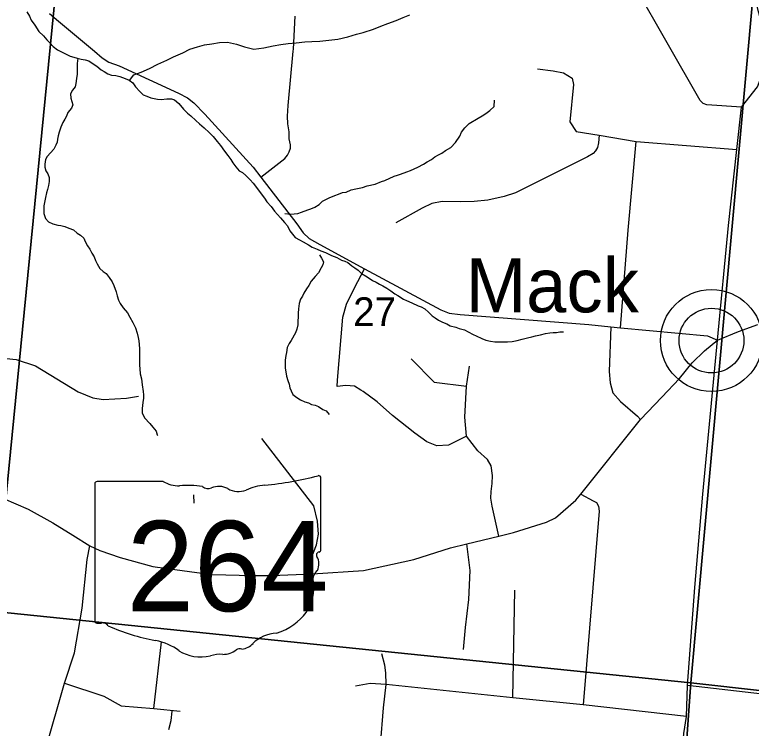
# Model space of a CAD drawing. Extents: x 0 to 43.4, y -8.1 to 22.
# Drawn here: x 4.976 to 6.05, y 19.427 to 20.468 of the extents above; entities that cross this region are included whole.
import ezdxf

# ---------------------------------------------------------------- set-up
doc = ezdxf.new("R2010")
doc.units = 0
for name, color, linetype in [('GM_X_Corporation', 7, 'Continuous'), ('GM_X_County_Road', 7, 'Continuous'), ('GM_X_Minor_River', 7, 'Continuous'), ('GM_X_Section_Text', 7, 'Continuous'), ('GM_X_State_Location', 7, 'Continuous'), ('GM_X_State_Route', 7, 'Continuous'), ('GM_X_State_Shield', 7, 'Continuous'), ('GM_X_Township_Road', 7, 'Continuous'), ('GM_X_Unincorporated', 7, 'Continuous'), ('GM_X_Unincorporated_Location', 7, 'Continuous'), ('GM_X_Unincorporated_Text', 7, 'Continuous')]:
    doc.layers.add(name, color=color, linetype=linetype)

msp = doc.modelspace()

# ---------------------------------------------------------------- linework, layer by layer
at = {"layer": 'GM_X_Corporation'}
for points in [[(4.0476, 20.7082), (5.0456, 20.604), (4.9462, 19.5972), (3.9403, 19.703)], [(6.0521, 20.4929), (5.9616, 19.4927), (4.9462, 19.5972), (5.0456, 20.604)], [(7.0465, 20.3953), (6.9413, 19.3833), (5.9616, 19.4927), (6.0521, 20.4929)], [(5.9616, 19.4927), (5.8893, 18.4791), (4.8473, 18.579), (4.9462, 19.5972)], [(5.9616, 19.4927), (6.9413, 19.3833), (6.8431, 18.3799), (5.8893, 18.4791)]]:
    msp.add_lwpolyline(points, close=True, dxfattribs=at)
at = {"layer": 'GM_X_County_Road'}
for points in [[(6.0357, 20.3327), (5.9847, 20.3361), (5.9794, 20.3381), (5.975, 20.3428), (5.8326, 20.592), (5.8291, 20.6012), (5.8268, 20.6093), (5.8263, 20.6196), (5.8283, 20.6466), (5.8319, 20.6972), (5.8303, 20.7167), (5.8274, 20.7335), (5.8218, 20.7469), (5.8142, 20.7586), (5.8035, 20.7684), (5.779, 20.7844), (5.7029, 20.8343), (5.6968, 20.8432), (5.6908, 20.8537), (5.6869, 20.8655), (5.6878, 20.9)], [(6.0357, 20.3327), (6.0589, 20.3624), (6.0642, 20.3767), (6.0699, 20.4347), (6.0514, 20.507), (6.0739, 20.9)], [(5.0263, 20.4697), (5.0396, 20.4585), (5.092, 20.4145), (5.1031, 20.4047), (5.1132, 20.3988), (5.1282, 20.3934), (5.2144, 20.3532), (5.2275, 20.3464), (5.2368, 20.3393), (5.2531, 20.3229), (5.3235, 20.2455), (5.3348, 20.2308), (5.3873, 20.1625), (5.3964, 20.1497), (5.4053, 20.1411), (5.4206, 20.1323), (5.4859, 20.0972)], [(6.0003, 19.9928), (6.0164, 20.1603), (6.0288, 20.2712), (6.0357, 20.3327)], [(5.4859, 20.0972), (5.5972, 20.0373), (5.6092, 20.0324), (5.6251, 20.0304), (5.813, 20.0156), (5.8451, 20.0124)], [(5.8451, 20.0124), (5.8423, 19.9471), (5.8438, 19.9306), (5.8477, 19.916), (5.8588, 19.9035), (5.8836, 19.8822), (5.8884, 19.8771)], [(5.8451, 20.0124), (5.859, 20.011), (5.9861, 19.9993), (6.0003, 19.9928)], [(5.9168, 18.9788), (5.9313, 19.1438), (5.9319, 19.1508), (5.942, 19.2909), (5.9466, 19.3546), (5.9513, 19.4191), (5.9555, 19.4438), (5.9566, 19.4892), (5.9673, 19.632), (5.979, 19.7684), (6.0003, 19.9928)], [(4.8412, 18.9443), (4.8517, 18.9555), (4.8735, 18.9849), (4.8771, 18.9917), (4.8807, 19.0109), (4.8872, 19.0868), (4.8907, 19.1269), (4.8957, 19.1416), (4.9044, 19.1555), (4.9529, 19.2503), (4.9786, 19.304), (4.9807, 19.309), (5.0206, 19.3955), (5.0483, 19.4922), (5.0629, 19.5365), (5.074, 19.6019), (5.0812, 19.673), (5.0855, 19.6927)], [(7.1544, 19.3549), (7.0147, 19.3696), (6.8713, 19.3847), (6.7437, 19.3982), (6.635, 19.4142), (6.3486, 19.4465), (6.2939, 19.453), (6.2651, 19.4537), (6.2278, 19.458), (6.1978, 19.4615), (6.1234, 19.47), (6.0534, 19.478), (5.9566, 19.4892)]]:
    msp.add_lwpolyline(points, dxfattribs=at)
at = {"layer": 'GM_X_Minor_River'}
for points in [[(4.9934, 20.4719), (4.9974, 20.4657), (4.9998, 20.4599), (5.0049, 20.4525), (5.011, 20.4435), (5.0176, 20.4369), (5.0227, 20.431), (5.0275, 20.4263), (5.0319, 20.4212), (5.0382, 20.4168), (5.0442, 20.4135), (5.049, 20.4111), (5.0565, 20.4074), (5.0617, 20.4057), (5.0666, 20.4044), (5.0727, 20.403), (5.0787, 20.4021), (5.0836, 20.4004), (5.0903, 20.3963), (5.0955, 20.3927), (5.1017, 20.3876), (5.1062, 20.3848), (5.1114, 20.3815), (5.1167, 20.3798), (5.1231, 20.3789), (5.1291, 20.3775), (5.137, 20.3746), (5.1426, 20.3721), (5.1478, 20.3685), (5.1518, 20.3627), (5.158, 20.3556), (5.1631, 20.3509), (5.1684, 20.3488), (5.174, 20.3467), (5.1793, 20.3454), (5.1838, 20.3445), (5.1891, 20.3439), (5.1975, 20.3451), (5.2043, 20.3453), (5.2088, 20.3436), (5.2151, 20.3381), (5.222, 20.3298), (5.2275, 20.3243), (5.2327, 20.3203), (5.24, 20.3136), (5.2452, 20.3085), (5.2522, 20.3026), (5.2592, 20.2959), (5.2651, 20.2903), (5.2709, 20.2829), (5.2756, 20.2771), (5.2818, 20.2685), (5.2865, 20.2626), (5.2908, 20.2564), (5.2937, 20.2517), (5.2981, 20.2459), (5.3032, 20.24), (5.3077, 20.2376), (5.3128, 20.2332), (5.3191, 20.2269), (5.3234, 20.2218), (5.3282, 20.2159), (5.3336, 20.2085), (5.3398, 20.2), (5.3434, 20.1949), (5.3496, 20.1878), (5.3547, 20.1812), (5.3591, 20.1765), (5.3635, 20.1714), (5.3693, 20.1647), (5.3737, 20.1596), (5.3768, 20.1523), (5.3809, 20.1476), (5.3845, 20.1429), (5.3908, 20.1393), (5.3964, 20.1364), (5.4042, 20.132), (5.4094, 20.1284), (5.4166, 20.1259), (5.4222, 20.1234), (5.4289, 20.1209), (5.4375, 20.1164), (5.4454, 20.1135), (5.4521, 20.1098), (5.4569, 20.1081), (5.4614, 20.1061), (5.4673, 20.1013), (5.4718, 20.0985), (5.4766, 20.0949), (5.4814, 20.0902), (5.4896, 20.0853), (5.4974, 20.0801), (5.5026, 20.0773), (5.5078, 20.0748), (5.5127, 20.0724), (5.5182, 20.0687), (5.5242, 20.0651), (5.5301, 20.0607)], [(5.143, 20.3718), (5.1496, 20.3801), (5.16, 20.384), (5.1723, 20.3893), (5.1846, 20.3954), (5.1977, 20.4015), (5.2073, 20.4062), (5.2208, 20.4123), (5.2312, 20.4177), (5.2423, 20.4211), (5.2523, 20.4239), (5.263, 20.4251), (5.2744, 20.4271), (5.2858, 20.4279), (5.299, 20.4249), (5.3107, 20.4211), (5.3243, 20.4173), (5.3388, 20.4195), (5.3525, 20.4226), (5.3636, 20.4242), (5.3743, 20.4257), (5.3861, 20.4269), (5.3986, 20.4281), (5.4089, 20.4286), (5.4207, 20.4294), (5.434, 20.4309), (5.447, 20.432), (5.4615, 20.4354), (5.4742, 20.4392), (5.4837, 20.442), (5.4987, 20.4469), (5.5095, 20.4512), (5.5198, 20.455), (5.5321, 20.4593), (5.5421, 20.4635), (5.5517, 20.4678)], [(5.0676, 20.4042), (5.0667, 20.3964), (5.0669, 20.3903), (5.0666, 20.3812), (5.066, 20.3748), (5.065, 20.3672), (5.0637, 20.3627), (5.0601, 20.3575), (5.0569, 20.3523), (5.0574, 20.3462), (5.0588, 20.3412), (5.0605, 20.3362), (5.0584, 20.3313), (5.0533, 20.325), (5.0512, 20.3198), (5.0487, 20.3153), (5.0459, 20.3105), (5.043, 20.3037), (5.0405, 20.2966), (5.0392, 20.2909), (5.0383, 20.2864), (5.0377, 20.2819), (5.0357, 20.2774), (5.0328, 20.2714), (5.0281, 20.2662), (5.023, 20.2611), (5.0205, 20.2566), (5.0195, 20.2498), (5.0198, 20.2452), (5.0211, 20.2402), (5.024, 20.2356), (5.0261, 20.2302), (5.0259, 20.2245), (5.0249, 20.2188), (5.0236, 20.2128), (5.0223, 20.2079), (5.0205, 20.2011), (5.0196, 20.1962), (5.0182, 20.1887), (5.018, 20.1826), (5.0182, 20.1776), (5.0206, 20.1703), (5.025, 20.1656), (5.0313, 20.1627), (5.0385, 20.1606), (5.043, 20.1604), (5.0487, 20.1587), (5.0546, 20.1562), (5.0614, 20.1537), (5.0669, 20.149), (5.0718, 20.1461), (5.0765, 20.1418), (5.0787, 20.1368), (5.0819, 20.1306), (5.0851, 20.1259), (5.0883, 20.1197), (5.0916, 20.1147), (5.0933, 20.1093), (5.0958, 20.1043), (5.0997, 20.0977), (5.1049, 20.0933), (5.1093, 20.0901), (5.1137, 20.0843), (5.118, 20.078), (5.1201, 20.0726), (5.1236, 20.0634), (5.1249, 20.0577), (5.1273, 20.0515), (5.1294, 20.0465), (5.1338, 20.0402), (5.14, 20.0328), (5.1436, 20.0266), (5.1479, 20.0188), (5.1521, 20.0107), (5.1541, 20.0031), (5.1558, 19.9969), (5.1568, 19.9919), (5.1574, 19.9866), (5.1575, 19.9805), (5.1577, 19.9752), (5.1579, 19.968), (5.1576, 19.9615), (5.1578, 19.9562), (5.1584, 19.9512), (5.1589, 19.944), (5.1606, 19.9363), (5.1618, 19.9275), (5.163, 19.918), (5.1636, 19.913), (5.1634, 19.9085), (5.1624, 19.902), (5.1614, 19.893), (5.1615, 19.8869), (5.1651, 19.8795), (5.1728, 19.8713), (5.1771, 19.8658), (5.1819, 19.8603), (5.1836, 19.8546), (5.1838, 19.8537)], [(5.3697, 20.1776), (5.3785, 20.177), (5.3834, 20.1772), (5.3884, 20.1778), (5.3937, 20.1795), (5.403, 20.1833), (5.4076, 20.1847), (5.4134, 20.1872), (5.4196, 20.1907), (5.4243, 20.1955), (5.4343, 20.2005), (5.4424, 20.204), (5.4478, 20.2061), (5.4536, 20.2082), (5.4589, 20.2091), (5.4662, 20.2123), (5.4731, 20.2136), (5.4827, 20.2155), (5.4896, 20.218), (5.5015, 20.2206), (5.5107, 20.2245), (5.5153, 20.2258), (5.5292, 20.2322), (5.5338, 20.2339), (5.5384, 20.2353), (5.5473, 20.2384), (5.5526, 20.2405), (5.5584, 20.2429), (5.5634, 20.2454), (5.5716, 20.2497), (5.577, 20.2529), (5.5836, 20.2565), (5.5882, 20.2602), (5.5937, 20.2634), (5.5987, 20.2659), (5.6041, 20.2699), (5.6115, 20.2742), (5.6186, 20.2815), (5.6246, 20.2904), (5.6271, 20.2964), (5.6319, 20.3027), (5.6385, 20.309), (5.6513, 20.3169), (5.6571, 20.3201), (5.6626, 20.3237), (5.6684, 20.3281), (5.6747, 20.3339), (5.6754, 20.343)], [(5.4201, 20.1174), (5.4233, 20.1127), (5.4262, 20.1073), (5.4249, 20.1028), (5.4224, 20.0983), (5.4188, 20.0912), (5.4137, 20.0857), (5.4081, 20.079), (5.4045, 20.0727), (5.4013, 20.0679), (5.3973, 20.0615), (5.3952, 20.057), (5.3924, 20.0526), (5.3903, 20.0462), (5.3896, 20.0386), (5.389, 20.0322), (5.3884, 20.0151), (5.3871, 20.0091), (5.385, 20.0038), (5.3789, 19.9926), (5.3761, 19.9882), (5.3732, 19.9822), (5.3719, 19.975), (5.3709, 19.9705), (5.3703, 19.9636), (5.3701, 19.9564), (5.3703, 19.9519), (5.3709, 19.9469), (5.3722, 19.9404), (5.3742, 19.9339), (5.3759, 19.9285), (5.3769, 19.9235), (5.3787, 19.9189), (5.3815, 19.9138), (5.3871, 19.9091), (5.3923, 19.9059), (5.399, 19.903), (5.4039, 19.9013), (5.4087, 19.8992), (5.4136, 19.8979), (5.4185, 19.8962), (5.4252, 19.8918), (5.4297, 19.8898), (5.4344, 19.8843)], [(5.5301, 20.0607), (5.5346, 20.0579), (5.5427, 20.0527), (5.5472, 20.0506), (5.5547, 20.0473), (5.5641, 20.0432), (5.5685, 20.0415), (5.5738, 20.0387), (5.5793, 20.0336), (5.5844, 20.0284), (5.5889, 20.0253), (5.5937, 20.0221), (5.5993, 20.0192), (5.606, 20.0167), (5.6109, 20.0139), (5.6188, 20.0121), (5.624, 20.01), (5.6315, 20.0078), (5.6368, 20.005), (5.6442, 20.0013), (5.6487, 19.9992), (5.6569, 19.9955), (5.6629, 19.9927), (5.6693, 19.9913), (5.6758, 19.9907), (5.6879, 19.9903), (5.6944, 19.9904), (5.7012, 19.991), (5.7085, 19.9922), (5.7157, 19.9943), (5.7234, 19.9963), (5.7299, 19.9979), (5.7349, 19.9993), (5.7422, 20.0009), (5.7498, 20.0026), (5.7559, 20.0035), (5.7609, 20.0041), (5.7658, 20.0043), (5.7708, 20.0049), (5.7761, 20.0051)], [(5.2375, 19.755), (5.2371, 19.7672)], [(5.2006, 19.4248), (5.2037, 19.438), (5.2052, 19.4516)]]:
    msp.add_lwpolyline(points, dxfattribs=at)
at = {"layer": 'GM_X_State_Route'}
msp.add_line((5.1803, 19.6621), (5.2595, 19.6515), dxfattribs=at)
for points in [[(5.9928, 19.9866), (6.0003, 19.9928), (6.0309, 20.0057), (6.0594, 20.0157)], [(5.9191, 19.9096), (5.9451, 19.9372), (5.9633, 19.96), (5.9817, 19.9772), (5.9928, 19.9866)], [(5.2595, 19.6515), (5.2635, 19.651), (5.323, 19.6493), (5.3504, 19.6497), (5.4101, 19.6519), (5.4843, 19.6566), (5.5575, 19.6731), (5.6113, 19.6897), (5.6351, 19.6955), (5.6817, 19.707), (5.7032, 19.7123), (5.7513, 19.7271), (5.7644, 19.7337), (5.7938, 19.7596), (5.8011, 19.7683), (5.8884, 19.8771), (5.9191, 19.9096)], [(4.9594, 19.7617), (4.9954, 19.7464), (5.0314, 19.7266), (5.0605, 19.7084)], [(5.0605, 19.7084), (5.0855, 19.6927), (5.0998, 19.6859), (5.1295, 19.6757), (5.1773, 19.6625), (5.1803, 19.6621)]]:
    msp.add_lwpolyline(points, dxfattribs=at)
at = {"layer": 'GM_X_State_Shield'}
for p, q in [((5.0926, 19.7834), (5.0926, 19.5833)), ((5.1924, 19.7869), (5.0959, 19.7869)), ((5.4222, 19.6871), (5.4222, 19.7918)), ((5.4222, 19.6872), (5.4222, 19.6871))]:
    msp.add_line(p, q, dxfattribs=at)
for centre, major_axis, start_param, end_param in [((5.3048, 20.0597), (0.3495, 0), 4.814394, 5.042369), ((5.4185, 19.7923), (0.00367, 0), 6.141152, 7.989035), ((5.0964, 19.7838), (0.00382, 0), 1.712693, 3.28349), ((5.2154, 19.8101), (0.037, 0), 4.042523, 4.731795), ((5.2276, 19.6745), (0.133, 0), 1.404758, 1.657858), ((5.2578, 19.7849), (0.0107, 0), 3.836095, 5.185415), ((5.2735, 19.7618), (0.0222, 0), 0.950623, 2.079405), ((5.3022, 19.7935), (0.0267, 0), 4.081561, 5.145723), ((5.3494, 19.7257), (0.0703, 0), 1.699011, 2.107814), ((5.4183, 19.6867), (0.00393, 0), 5.05454, 6.418171), ((5.4213, 19.6795), (0.00568, 0), 1.883978, 3.671073), ((5.3852, 19.6662), (0.0341, 0), 5.934695, 6.695948), ((5.4353, 19.6433), (0.0248, 0), 2.387724, 3.262537), ((5.3244, 19.63), (0.0874, 0), 5.101752, 6.440018), ((5.0964, 19.5829), (0.00385, 0), 3.00124, 4.508301), ((5.097, 19.6033), (0.0294, 0), 4.665946, 4.897461), ((5.103, 19.5718), (0.0106, 0), 0.519207, 1.627899), ((5.2368, 19.7516), (0.2524, 0), 4.195997, 4.488961), ((5.3612, 19.5271), (0.0479, 0), 1.647645, 2.488434), ((5.1616, 19.4934), (0.079, 0), 0.823519, 1.323587), ((5.3006, 19.5639), (0.0282, 0), 4.937069, 5.64225), ((5.247, 19.5708), (0.0501, 0), 4.026481, 4.996735), ((5.2796, 19.5558), (0.0267, 0), 4.691044, 5.507374), ((5.3038, 19.5364), (0.00752, 0), 1.147584, 2.315152), ((5.276, 19.5016), (0.0412, 0), 1.495662, 1.94098)]:
    msp.add_ellipse(centre, major_axis=major_axis, ratio=0.8, start_param=start_param, end_param=end_param, dxfattribs=at)
at = {"layer": 'GM_X_Township_Road'}
for p, q in [((5.702, 19.4711), (5.7049, 19.6283)), ((5.1785, 19.4554), (5.1897, 19.5526))]:
    msp.add_line(p, q, dxfattribs=at)
for points in [[(5.3818, 20.4145), (5.3821, 20.4175), (5.3849, 20.4659)], [(5.3348, 20.2308), (5.3694, 20.2582), (5.3734, 20.2629), (5.3758, 20.2675), (5.3777, 20.2729), (5.3777, 20.2777), (5.3757, 20.2865), (5.3757, 20.2967), (5.3738, 20.3085), (5.3737, 20.3197), (5.3746, 20.3352), (5.3818, 20.4145)], [(5.7382, 20.3888), (5.7609, 20.3858), (5.776, 20.3828), (5.7887, 20.3751), (5.7903, 20.3661), (5.7853, 20.3115), (5.7943, 20.2975), (5.8278, 20.2918)], [(5.8278, 20.2918), (5.8268, 20.281), (5.8253, 20.274), (5.8226, 20.269), (5.8191, 20.2652), (5.811, 20.2602), (5.7058, 20.208), (5.6892, 20.2027), (5.6656, 20.1974), (5.6458, 20.1954), (5.6262, 20.1949), (5.5988, 20.1952), (5.584, 20.1923), (5.5699, 20.1857), (5.5313, 20.1641)], [(5.8278, 20.2918), (5.882, 20.2828), (6.0288, 20.2712)], [(5.859, 20.011), (5.8703, 20.1533), (5.882, 20.2828)], [(5.4802, 19.9201), (5.4714, 19.926), (5.4586, 19.9269), (5.4461, 19.9255), (5.4462, 19.9344), (5.4541, 20.0267), (5.4593, 20.0456), (5.4714, 20.0691), (5.4859, 20.0972)], [(4.8794, 19.9495), (4.9286, 19.9661), (4.9541, 19.9673), (4.9777, 19.9648), (5.006, 19.9555), (5.0683, 19.9175), (5.0895, 19.9089), (5.1048, 19.9061), (5.1389, 19.9081), (5.1561, 19.911)], [(5.5539, 19.9656), (5.5875, 19.9318), (5.6346, 19.926)], [(5.6817, 19.707), (5.672, 19.7507), (5.6699, 19.7626), (5.6704, 19.7719), (5.6717, 19.7838), (5.6722, 19.7954), (5.6706, 19.8093), (5.6653, 19.8189), (5.651, 19.8312), (5.6346, 19.8526), (5.6323, 19.8804), (5.6346, 19.926), (5.6387, 19.9552)], [(5.6346, 19.8526), (5.6081, 19.8398), (5.591, 19.8388), (5.5767, 19.8444), (5.5594, 19.8572), (5.5266, 19.8831), (5.5042, 19.9027), (5.4837, 19.9178), (5.4802, 19.9201)], [(5.4101, 19.6519), (5.4069, 19.6719), (5.416, 19.6942), (5.4188, 19.7097), (5.4174, 19.7288), (5.4119, 19.7512), (5.3363, 19.8496)], [(5.8011, 19.7683), (5.8191, 19.7583), (5.8239, 19.7559), (5.8271, 19.7505), (5.828, 19.7432), (5.8045, 19.4607)], [(5.63, 19.5413), (5.6332, 19.5735), (5.6381, 19.6144), (5.64, 19.6566), (5.6351, 19.6955)], [(5.5057, 19.3601), (5.5077, 19.3816), (5.509, 19.4017), (5.5137, 19.4564), (5.5175, 19.4906), (5.5167, 19.5074), (5.5154, 19.5189), (5.5112, 19.5354)], [(5.0483, 19.4922), (5.1056, 19.4736), (5.1311, 19.4595), (5.1785, 19.4554), (5.2168, 19.4517)], [(5.9555, 19.4438), (5.8045, 19.4607), (5.702, 19.4711), (5.5175, 19.4906), (5.4938, 19.4918), (5.4724, 19.4878)]]:
    msp.add_lwpolyline(points, dxfattribs=at)
at = {"layer": 'GM_X_Unincorporated'}
for radius in [0.0744, 0.0472]:
    msp.add_circle((5.9917, 19.9923), radius, dxfattribs=at)
at = {"layer": 'GM_X_Unincorporated_Location'}
msp.add_line((5.9917, 19.9923), (5.9917, 19.9923), dxfattribs=at)

# ---------------------------------------------------------------- texts
at = {"layer": 'GM_X_Section_Text'}
msp.add_text('27', height=0.04186, rotation=0, dxfattribs=at).set_placement((5.4693, 20.0136))
at = {"layer": 'GM_X_State_Location'}
for s in ['s', 'r']:
    msp.add_text(s, height=0.000189, dxfattribs=at).set_placement((5.2537, 19.6701))
msp.add_text('264', height=0.000189, rotation=0, dxfattribs=at).set_placement((5.1868, 19.6563))
at = {"layer": 'GM_X_State_Shield'}
msp.add_text('264', height=0.13184, dxfattribs=at).set_placement((5.1391, 19.5974))
at = {"layer": 'GM_X_Unincorporated_Text'}
msp.add_text('Mack', height=0.07898, rotation=0, dxfattribs=at).set_placement((5.6335, 20.0335))

doc.saveas('drawing.dxf')
